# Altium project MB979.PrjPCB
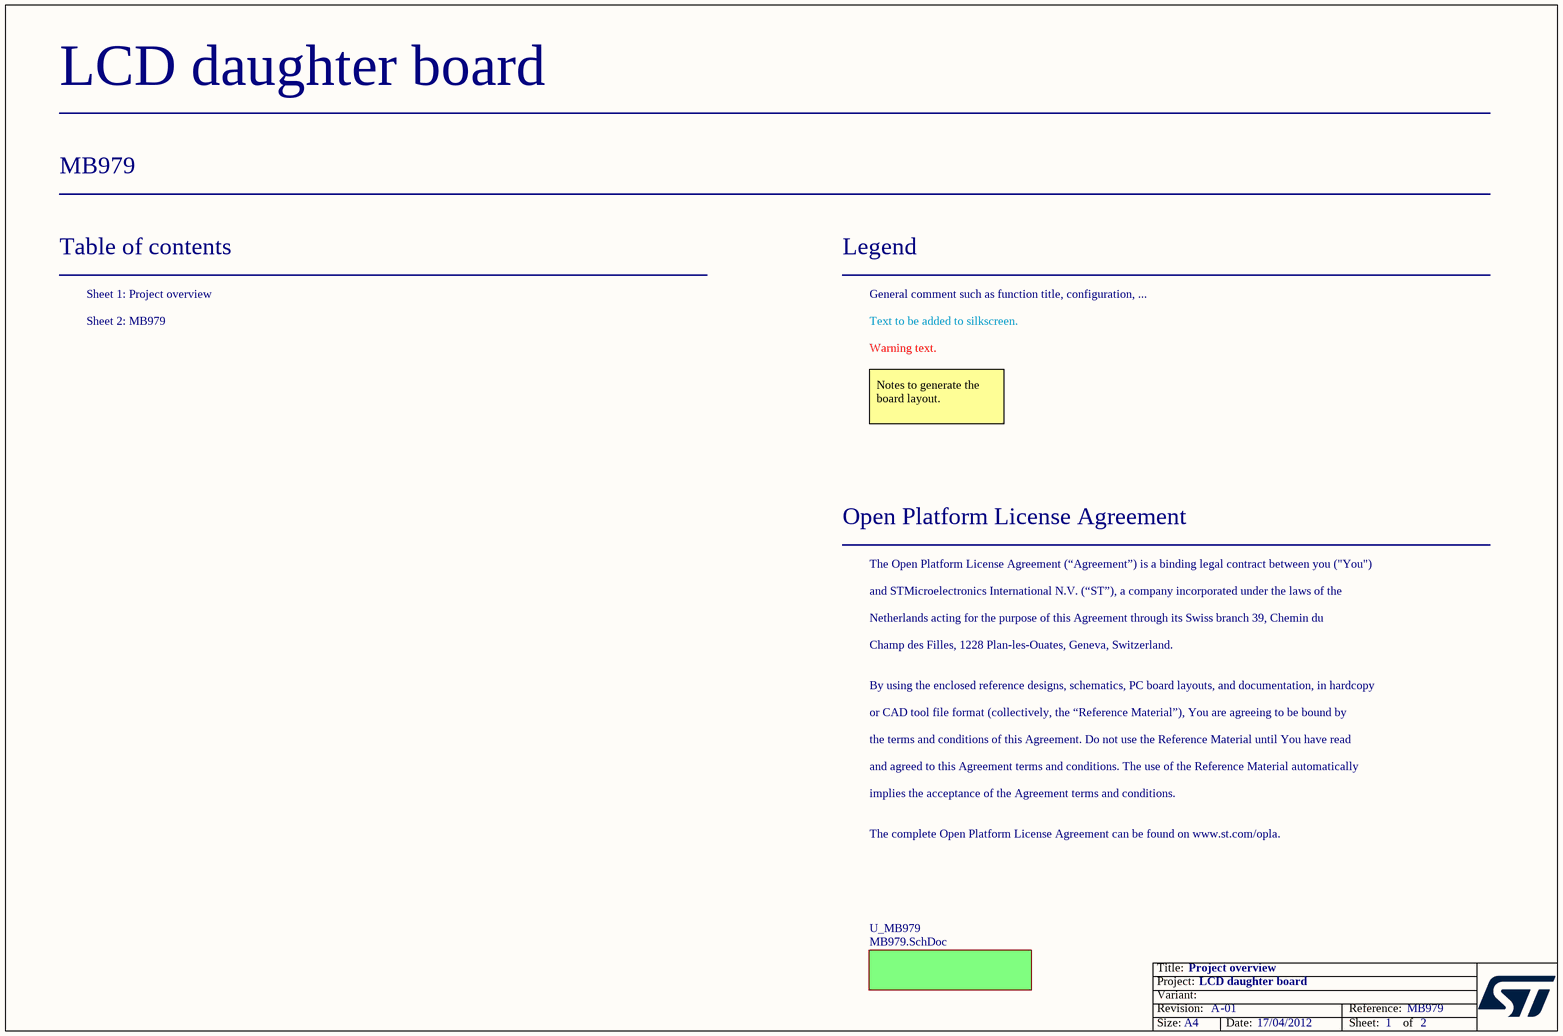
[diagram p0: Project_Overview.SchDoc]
Board_Assembly_Revision: 01; Board_Document_Date: 17/04/2012; Board_Name: LCD daughter board; Board_PCB_Revision: A; Board_Reference: MB979
2 sheets, 6 parts. Net scope: global (net labels, ports and power ports of the same name join across sheets).
Board file: MB979.PCBDOC
Sheets:
  Project_Overview.SchDoc
    U_MB979 = MB979.SchDoc

## Sheet Project_Overview.SchDoc: Project overview
size A4; Date: Not used; ApprovedBy: Not used; CheckedBy: Not used; Author: Not used; CompanyName: STMicroelectronics; DrawnBy: Not used; Engineer: Not used; Organization: Not used; Address1: Not used; Address2: Not used; Address3: Not used; Address4: Not used; DocumentNumber: 1; Revision: Not used; SheetNumber: 1; SheetTotal: 2

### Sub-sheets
U_MB979 = MB979.SchDoc: no entries

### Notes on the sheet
- Table of contents
- Sheet 1: Project overview
- Legend
- General comment such as function title, configuration, ...
- Sheet 2: MB979
- Text to be added to silkscreen.
- Warning text.
- Notes to generate the board layout.
- Open Platform License Agreement
- The Open Platform License Agreement (“Agreement”) is a binding legal contract between you ("You")
- and STMicroelectronics International N.V. (“ST”), a company incorporated under the laws of the
- Netherlands acting for the purpose of this Agreement through its Swiss branch 39, Chemin du
- Champ des Filles, 1228 Plan-les-Ouates, Geneva, Switzerland.
- By using the enclosed reference designs, schematics, PC board layouts, and documentation, in hardcopy
- or CAD tool file format (collectively, the “Reference Material”), You are agreeing to be bound by
- the terms and conditions of this Agreement. Do not use the Reference Material until You have read
- and agreed to this Agreement terms and conditions. The use of the Reference Material automatically
- implies the acceptance of the Agreement terms and conditions.
- The complete Open Platform License Agreement can be found on www.st.com/opla.

## Sheet MB979.SchDoc: LCD glass module
size A4; DocumentNumber: 2; Revision: A.1[PCB.SCH]; SheetNumber: 2; SheetTotal: 2
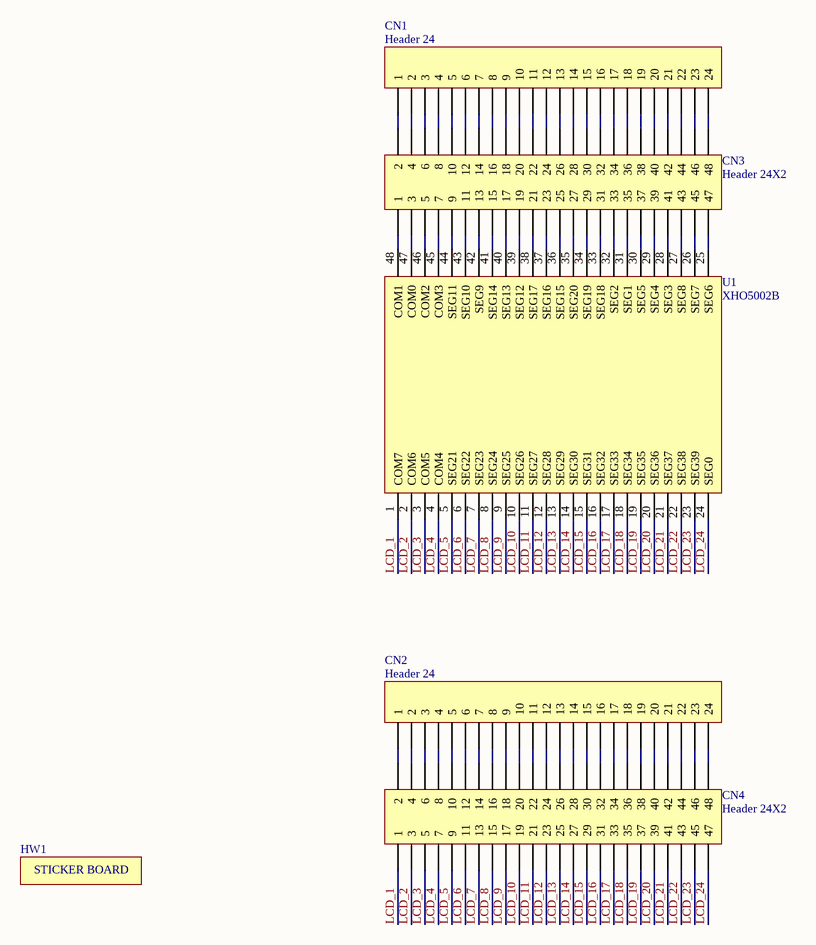
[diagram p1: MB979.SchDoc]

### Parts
CN1  Header 24  [HDR1X24]
CN2  Header 24  [HDR1X24]
CN3  Header 24X2  [HDR2X24]
CN4  Header 24X2  [HDR2X24]
HW1  STICKER_BOARD  (value not drawn)  (no BOM)
U1  XHO5002B

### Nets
LCD_1: CN4.1 U1.1(COM7)
LCD_2: CN4.3 U1.2(COM6)
LCD_3: CN4.5 U1.3(COM5)
LCD_4: CN4.7 U1.4(COM4)
LCD_5: CN4.9 U1.5(SEG21)
LCD_6: CN4.11 U1.6(SEG22)
LCD_7: CN4.13 U1.7(SEG23)
LCD_8: CN4.15 U1.8(SEG24)
LCD_9: CN4.17 U1.9(SEG25)
LCD_10: CN4.19 U1.10(SEG26)
LCD_11: CN4.21 U1.11(SEG27)
LCD_12: CN4.23 U1.12(SEG28)
LCD_13: CN4.25 U1.13(SEG29)
LCD_14: CN4.27 U1.14(SEG30)
LCD_15: CN4.29 U1.15(SEG31)
LCD_16: CN4.31 U1.16(SEG32)
LCD_17: CN4.33 U1.17(SEG33)
LCD_18: CN4.35 U1.18(SEG34)
LCD_19: CN4.37 U1.19(SEG35)
LCD_20: CN4.39 U1.20(SEG36)
LCD_21: CN4.41 U1.21(SEG37)
LCD_22: CN4.43 U1.22(SEG38)
LCD_23: CN4.45 U1.23(SEG39)
LCD_24: CN4.47 U1.24(SEG0)
NetCN1_1: CN1.1 CN3.2
NetCN1_2: CN1.2 CN3.4
NetCN1_3: CN1.3 CN3.6
NetCN1_4: CN1.4 CN3.8
NetCN1_5: CN1.5 CN3.10
NetCN1_6: CN1.6 CN3.12
NetCN1_7: CN1.7 CN3.14
NetCN1_8: CN1.8 CN3.16
NetCN1_9: CN1.9 CN3.18
NetCN1_10: CN1.10 CN3.20
NetCN1_11: CN1.11 CN3.22
NetCN1_12: CN1.12 CN3.24
NetCN1_13: CN1.13 CN3.26
NetCN1_14: CN1.14 CN3.28
NetCN1_15: CN1.15 CN3.30
NetCN1_16: CN1.16 CN3.32
NetCN1_17: CN1.17 CN3.34
NetCN1_18: CN1.18 CN3.36
NetCN1_19: CN1.19 CN3.38
NetCN1_20: CN1.20 CN3.40
NetCN1_21: CN1.21 CN3.42
NetCN1_22: CN1.22 CN3.44
NetCN1_23: CN1.23 CN3.46
NetCN1_24: CN1.24 CN3.48
NetCN2_1: CN2.1 CN4.2
NetCN2_2: CN2.2 CN4.4
NetCN2_3: CN2.3 CN4.6
NetCN2_4: CN2.4 CN4.8
NetCN2_5: CN2.5 CN4.10
NetCN2_6: CN2.6 CN4.12
NetCN2_7: CN2.7 CN4.14
NetCN2_8: CN2.8 CN4.16
NetCN2_9: CN2.9 CN4.18
NetCN2_10: CN2.10 CN4.20
NetCN2_11: CN2.11 CN4.22
NetCN2_12: CN2.12 CN4.24
NetCN2_13: CN2.13 CN4.26
NetCN2_14: CN2.14 CN4.28
NetCN2_15: CN2.15 CN4.30
NetCN2_16: CN2.16 CN4.32
NetCN2_17: CN2.17 CN4.34
NetCN2_18: CN2.18 CN4.36
NetCN2_19: CN2.19 CN4.38
NetCN2_20: CN2.20 CN4.40
NetCN2_21: CN2.21 CN4.42
NetCN2_22: CN2.22 CN4.44
NetCN2_23: CN2.23 CN4.46
NetCN2_24: CN2.24 CN4.48
NetCN3_1: CN3.1 U1.48(COM1)
NetCN3_3: CN3.3 U1.47(COM0)
NetCN3_5: CN3.5 U1.46(COM2)
NetCN3_7: CN3.7 U1.45(COM3)
NetCN3_9: CN3.9 U1.44(SEG11)
NetCN3_11: CN3.11 U1.43(SEG10)
NetCN3_13: CN3.13 U1.42(SEG9)
NetCN3_15: CN3.15 U1.41(SEG14)
NetCN3_17: CN3.17 U1.40(SEG13)
NetCN3_19: CN3.19 U1.39(SEG12)
NetCN3_21: CN3.21 U1.38(SEG17)
NetCN3_23: CN3.23 U1.37(SEG16)
NetCN3_25: CN3.25 U1.36(SEG15)
NetCN3_27: CN3.27 U1.35(SEG20)
NetCN3_29: CN3.29 U1.34(SEG19)
NetCN3_31: CN3.31 U1.33(SEG18)
NetCN3_33: CN3.33 U1.32(SEG2)
NetCN3_35: CN3.35 U1.31(SEG1)
NetCN3_37: CN3.37 U1.30(SEG5)
NetCN3_39: CN3.39 U1.29(SEG4)
NetCN3_41: CN3.41 U1.28(SEG3)
NetCN3_43: CN3.43 U1.27(SEG8)
NetCN3_45: CN3.45 U1.26(SEG7)
NetCN3_47: CN3.47 U1.25(SEG6)

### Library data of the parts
CN1 CN2 = Header 24: Header, 24-Pin
CN3 CN4 = Header 24X2: Header, 24-Pin, Dual row
U1 = XHO5002

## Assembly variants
Default: all parts fitted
